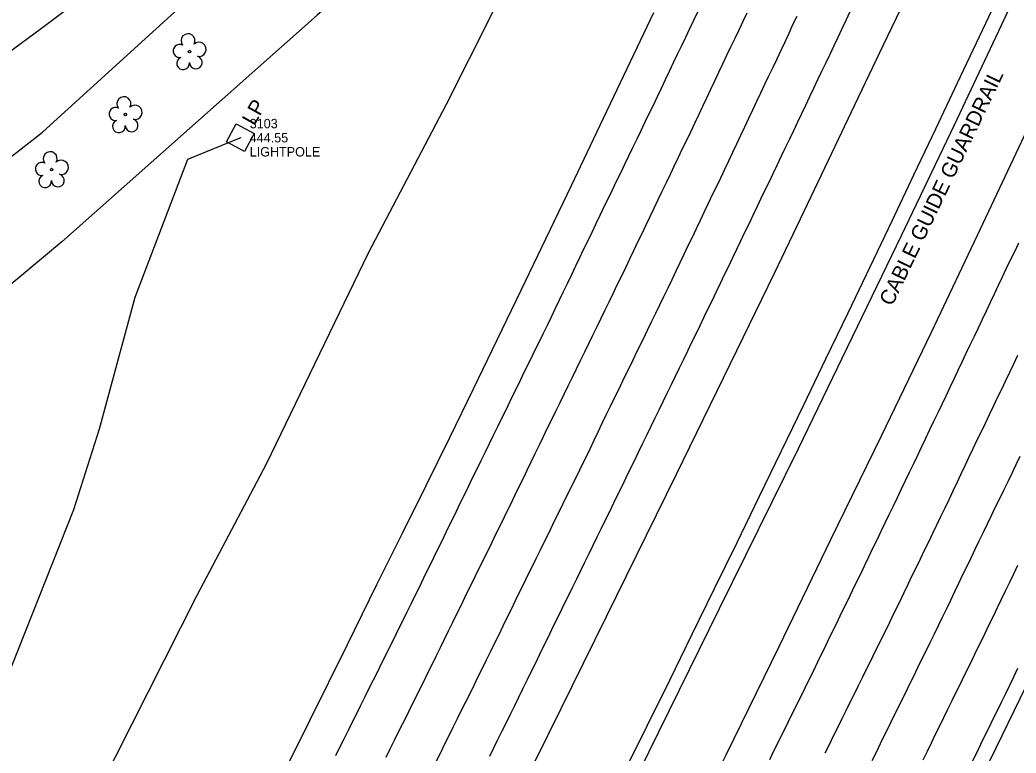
# Model space of a CAD drawing. Extents: x 2074109 to 2077820, y 741079 to 746031.
# Drawn here: x 2075699.8 to 2075964.7, y 743972 to 744166.9 of the extents above; entities that cross this region are included whole.
import ezdxf

# ---------------------------------------------------------------- set-up
doc = ezdxf.new("R2010")
doc.units = 0
for name, color, linetype in [('Exist Guardrail Cable Guide Rail', 7, 'Continuous'), ('Exist Guardrail Cable Guide Rail Text', 7, 'Continuous'), ('Exist Horizontal Alignment', 7, 'Continuous'), ('Exist Roads EOP', 7, 'Continuous'), ('Exist Roads EOT', 7, 'Continuous'), ('Exist Structure Minor Paved Ditch or Gutter', 7, 'Continuous'), ('Exist Utilities Other Pole Cogo Comment', 7, 'Continuous'), ('Exist Utilities Other Pole Cogo Elevation', 7, 'Continuous'), ('Exist Utilities Other Pole Cogo Number', 7, 'Continuous'), ('Exist Utilities Other Pole Text', 7, 'Continuous'), ('Exist Utilities Other Pole With Base CELL', 7, 'Continuous'), ('Exist Utilities Power UG Cable SUE LOS B', 7, 'Continuous'), ('Exist Utilities Telephone UG FO SUE LOS B', 7, 'Continuous'), ('Exist Vegetation Hedge Row', 7, 'Continuous'), ('Exist Vegetation Tree CELL', 7, 'Continuous')]:
    doc.layers.add(name, color=color, linetype=linetype)

msp = doc.modelspace()

# ---------------------------------------------------------------- linework, layer by layer
at = {"layer": 'Exist Guardrail Cable Guide Rail'}
for points in [[(2075948.31, 744139.02), (2075989.39, 744226.34), (2076023.39, 744300.35), (2076049.61, 744359.61), (2076088.84, 744447.64), (2076120.46, 744520.55), (2076157.81, 744608.48)], [(2075650.49, 743554.11), (2075673.2, 743596.24), (2075687.81, 743623.41), (2075710.4, 743665.84), (2075732.48, 743708.32), (2075762.33, 743765.12), (2075783.84, 743808.03), (2075814.02, 743866.81), (2075836.08, 743909.75), (2075849.04, 743935.68), (2075864.46, 743966.93), (2075885.81, 744010.38), (2075906.82, 744052.95), (2075934.19, 744109.59), (2075948.31, 744139.02)]]:
    msp.add_lwpolyline(points, dxfattribs=at)
at = {"layer": 'Exist Horizontal Alignment'}
msp.add_arc((2065746.77, 748969.72), 11283.45, 330.581241, 339.398504, dxfattribs=at)
at = {"layer": 'Exist Roads EOP'}
for points in [[(2075836.75, 743969.63), (2075843.73, 743983.78), (2075855.79, 744008.27), (2075874.4, 744046.14), (2075890.48, 744078.97), (2075900.48, 744099.6), (2075908.34, 744116.01), (2075915.68, 744131.47), (2075922.69, 744146.17), (2075929.46, 744160.26), (2075936.35, 744174.77), (2075943.56, 744190.29), (2075952.83, 744210.32), (2075964.71, 744235.96)], [(2075763.5, 743953.67), (2075776.94, 743980.59), (2075786.97, 744000.87), (2075794.77, 744016.74), (2075801.53, 744030.43), (2075807.8, 744043.11), (2075814.12, 744055.91), (2075820.45, 744068.82), (2075826.74, 744081.8), (2075833.13, 744095.06), (2075839.73, 744108.84), (2075846.46, 744122.91), (2075853.25, 744137.07), (2075860.44, 744152.12), (2075868.38, 744168.9)], [(2075967.54, 744137.56), (2075955.17, 744111.24), (2075942.12, 744083.79), (2075928.82, 744056.24), (2075915.37, 744028.68), (2075901.58, 744000.21), (2075887.58, 743971.62), (2075873.68, 743943.73), (2075859.47, 743915.43), (2075845.49, 743887.94), (2075831.95, 743861.25), (2075818.67, 743835.19), (2075805.35, 743809.58), (2075791.14, 743782.17), (2075777.02, 743754.87), (2075762.95, 743727.43), (2075748.9, 743700.45), (2075734.98, 743673.94), (2075720.91, 743647.46), (2075706.73, 743621.16), (2075693.58, 743599.01), (2075681.89, 743583.08), (2075669.6, 743566.23)], [(2075970.53, 743996.41), (2075954.43, 743963.28), (2075936.6, 743927.16), (2075918.49, 743891.12), (2075900.94, 743856.17), (2075884.58, 743824.12), (2075866.92, 743789.7), (2075848.76, 743754.48), (2075829.89, 743717.88), (2075811.7, 743682.72), (2075794.27, 743649.52), (2075774.29, 743611.67), (2075753.6, 743572.88), (2075735, 743538.43)]]:
    msp.add_lwpolyline(points, dxfattribs=at)
at = {"layer": 'Exist Roads EOT'}
for points in [[(2075783.81, 743971.31), (2075784.93, 743973.54), (2075786.04, 743975.78), (2075787.16, 743978.02), (2075788.27, 743980.26), (2075789.39, 743982.49), (2075790.5, 743984.73), (2075791.62, 743986.97), (2075792.73, 743989.21), (2075793.84, 743991.45), (2075794.95, 743993.69), (2075796.06, 743995.93), (2075797.17, 743998.17), (2075798.28, 744000.41), (2075799.39, 744002.64), (2075800.5, 744004.88), (2075801.61, 744007.12), (2075802.72, 744009.36), (2075803.83, 744011.6), (2075804.94, 744013.84), (2075806.04, 744016.09), (2075807.14, 744018.34), (2075808.24, 744020.58), (2075809.34, 744022.83), (2075810.43, 744025.07), (2075811.53, 744027.32), (2075812.63, 744029.56), (2075813.73, 744031.81), (2075814.82, 744034.06), (2075815.92, 744036.3), (2075817.01, 744038.55), (2075818.1, 744040.8), (2075819.2, 744043.05), (2075820.29, 744045.29), (2075821.39, 744047.54), (2075822.48, 744049.79), (2075823.58, 744052.04), (2075824.67, 744054.28), (2075825.77, 744056.53), (2075826.87, 744058.77), (2075827.97, 744061.02), (2075829.07, 744063.26), (2075830.17, 744065.51), (2075831.27, 744067.75), (2075832.37, 744070), (2075833.46, 744072.25), (2075834.56, 744074.49), (2075835.66, 744076.74), (2075836.76, 744078.98), (2075837.86, 744081.23), (2075838.96, 744083.47), (2075840.06, 744085.72), (2075841.15, 744087.97), (2075842.23, 744090.22), (2075843.31, 744092.48), (2075844.39, 744094.73), (2075845.47, 744096.98), (2075846.55, 744099.24), (2075847.63, 744101.49), (2075848.71, 744103.75), (2075849.79, 744106), (2075850.88, 744108.25), (2075851.96, 744110.51), (2075853.04, 744112.76), (2075854.12, 744115.01), (2075855.21, 744117.26), (2075856.3, 744119.52), (2075857.38, 744121.77), (2075858.47, 744124.02), (2075859.56, 744126.27), (2075860.65, 744128.52), (2075861.73, 744130.77), (2075862.82, 744133.02), (2075863.91, 744135.27), (2075864.99, 744137.52), (2075866.08, 744139.78), (2075867.17, 744142.03), (2075868.24, 744144.28), (2075869.32, 744146.54), (2075870.4, 744148.8), (2075871.47, 744151.05), (2075872.55, 744153.31), (2075873.63, 744155.56), (2075874.7, 744157.82), (2075875.78, 744160.08), (2075876.86, 744162.33), (2075877.93, 744164.59), (2075879.01, 744166.85), (2075880.08, 744169.1)], [(2075893.08, 744168.72), (2075892.01, 744166.46), (2075890.94, 744164.2), (2075889.87, 744161.94), (2075888.8, 744159.68), (2075887.73, 744157.42), (2075886.66, 744155.17), (2075885.59, 744152.91), (2075884.52, 744150.65), (2075883.45, 744148.39), (2075882.38, 744146.13), (2075881.31, 744143.87), (2075880.24, 744141.61), (2075879.17, 744139.35), (2075878.1, 744137.09), (2075877.02, 744134.84), (2075875.93, 744132.59), (2075874.85, 744130.34), (2075873.76, 744128.08), (2075872.68, 744125.83), (2075871.61, 744123.57), (2075870.53, 744121.32), (2075869.45, 744119.06), (2075868.38, 744116.8), (2075867.3, 744114.55), (2075866.23, 744112.29), (2075865.15, 744110.03), (2075864.07, 744107.78), (2075863, 744105.52), (2075861.92, 744103.27), (2075860.85, 744101.01), (2075859.76, 744098.76), (2075858.66, 744096.51), (2075857.56, 744094.27), (2075856.47, 744092.02), (2075855.37, 744089.77), (2075854.28, 744087.52), (2075853.18, 744085.28), (2075852.09, 744083.03), (2075851, 744080.78), (2075849.9, 744078.53), (2075848.81, 744076.28), (2075847.72, 744074.04), (2075846.62, 744071.79), (2075845.53, 744069.54), (2075844.44, 744067.29), (2075843.34, 744065.05), (2075842.25, 744062.8), (2075841.15, 744060.55), (2075840.05, 744058.31), (2075838.96, 744056.06), (2075837.86, 744053.81), (2075836.77, 744051.56), (2075835.68, 744049.31), (2075834.59, 744047.06), (2075833.5, 744044.82), (2075832.4, 744042.57), (2075831.31, 744040.32), (2075830.22, 744038.07), (2075829.13, 744035.82), (2075828.04, 744033.57), (2075826.94, 744031.32), (2075825.85, 744029.08), (2075824.74, 744026.84), (2075823.63, 744024.6), (2075822.52, 744022.36), (2075821.41, 744020.11), (2075820.32, 744017.87), (2075819.22, 744015.62), (2075818.12, 744013.38), (2075817.02, 744011.13), (2075815.92, 744008.89), (2075814.83, 744006.64), (2075813.73, 744004.4), (2075812.63, 744002.15), (2075811.53, 743999.9), (2075810.43, 743997.66), (2075809.33, 743995.41), (2075808.23, 743993.17), (2075807.12, 743990.93), (2075806.01, 743988.69), (2075804.9, 743986.45), (2075803.79, 743984.21), (2075802.67, 743981.98), (2075801.56, 743979.74), (2075800.44, 743977.5), (2075799.33, 743975.26), (2075798.21, 743973.02), (2075797.1, 743970.79)], [(2075810.6, 743969.9), (2075811.71, 743972.15), (2075812.82, 743974.39), (2075813.92, 743976.63), (2075815.03, 743978.87), (2075816.14, 743981.11), (2075817.26, 743983.34), (2075818.38, 743985.58), (2075819.5, 743987.81), (2075820.61, 743990.05), (2075821.71, 743992.3), (2075822.81, 743994.54), (2075823.91, 743996.79), (2075825.01, 743999.03), (2075826.11, 744001.28), (2075827.21, 744003.52), (2075828.3, 744005.77), (2075829.4, 744008.02), (2075830.5, 744010.26), (2075831.6, 744012.51), (2075832.7, 744014.75), (2075833.8, 744017), (2075834.9, 744019.24), (2075836, 744021.48), (2075837.11, 744023.73), (2075838.21, 744025.97), (2075839.31, 744028.21), (2075840.42, 744030.46), (2075841.52, 744032.7), (2075842.62, 744034.94), (2075843.72, 744037.19), (2075844.83, 744039.43), (2075845.93, 744041.67), (2075847.03, 744043.92), (2075848.14, 744046.16), (2075849.24, 744048.4), (2075850.34, 744050.65), (2075851.43, 744052.9), (2075852.5, 744055.16), (2075853.57, 744057.41), (2075854.65, 744059.67), (2075855.74, 744061.92), (2075856.84, 744064.17), (2075857.93, 744066.41), (2075859.03, 744068.66), (2075860.12, 744070.91), (2075861.22, 744073.15), (2075862.31, 744075.4), (2075863.41, 744077.65), (2075864.5, 744079.9), (2075865.6, 744082.14), (2075866.7, 744084.39), (2075867.79, 744086.64), (2075868.88, 744088.89), (2075869.97, 744091.14), (2075871.05, 744093.39), (2075872.14, 744095.64), (2075873.22, 744097.9), (2075874.3, 744100.15), (2075875.38, 744102.41), (2075876.46, 744104.66), (2075877.53, 744106.92), (2075878.61, 744109.17), (2075879.69, 744111.43), (2075880.77, 744113.68), (2075881.85, 744115.94), (2075882.93, 744118.19), (2075884.01, 744120.45), (2075885.09, 744122.7), (2075886.15, 744124.96), (2075887.22, 744127.22), (2075888.29, 744129.48), (2075889.36, 744131.74), (2075890.43, 744134), (2075891.5, 744136.26), (2075892.57, 744138.52), (2075893.64, 744140.78), (2075894.71, 744143.04), (2075895.78, 744145.3), (2075896.85, 744147.55), (2075897.92, 744149.81), (2075898.99, 744152.07), (2075900.06, 744154.33), (2075901.13, 744156.59), (2075902.2, 744158.85), (2075903.26, 744161.12), (2075904.31, 744163.38), (2075905.37, 744165.65), (2075906.44, 744167.91)], [(2075920.47, 744169.05), (2075919.4, 744166.79), (2075918.33, 744164.53), (2075917.26, 744162.27), (2075916.2, 744160.01), (2075915.13, 744157.75), (2075914.06, 744155.49), (2075912.99, 744153.23), (2075911.92, 744150.96), (2075910.86, 744148.7), (2075909.79, 744146.44), (2075908.72, 744144.18), (2075907.64, 744141.93), (2075906.56, 744139.68), (2075905.48, 744137.42), (2075904.4, 744135.17), (2075903.32, 744132.91), (2075902.24, 744130.66), (2075901.16, 744128.4), (2075900.08, 744126.15), (2075899, 744123.89), (2075897.92, 744121.64), (2075896.84, 744119.39), (2075895.76, 744117.13), (2075894.68, 744114.88), (2075893.6, 744112.62), (2075892.52, 744110.37), (2075891.43, 744108.12), (2075890.35, 744105.86), (2075889.27, 744103.61), (2075888.18, 744101.36), (2075887.1, 744099.1), (2075886.02, 744096.85), (2075884.93, 744094.6), (2075883.85, 744092.34), (2075882.77, 744090.09), (2075881.69, 744087.84), (2075880.6, 744085.59), (2075879.5, 744083.34), (2075878.41, 744081.09), (2075877.32, 744078.84), (2075876.23, 744076.59), (2075875.13, 744074.35), (2075874.04, 744072.1), (2075872.95, 744069.85), (2075871.86, 744067.6), (2075870.77, 744065.35), (2075869.67, 744063.1), (2075868.58, 744060.86), (2075867.49, 744058.61), (2075866.4, 744056.36), (2075865.3, 744054.11), (2075864.21, 744051.86), (2075863.12, 744049.61), (2075862.03, 744047.36), (2075860.93, 744045.12), (2075859.84, 744042.87), (2075858.75, 744040.62), (2075857.65, 744038.37), (2075856.55, 744036.13), (2075855.46, 744033.88), (2075854.36, 744031.64), (2075853.26, 744029.39), (2075852.16, 744027.14), (2075851.06, 744024.9), (2075849.96, 744022.65), (2075848.87, 744020.41), (2075847.77, 744018.16), (2075846.67, 744015.92), (2075845.57, 744013.67), (2075844.47, 744011.43), (2075843.37, 744009.18), (2075842.27, 744006.94), (2075841.18, 744004.69), (2075840.08, 744002.44), (2075838.98, 744000.2), (2075837.88, 743997.95), (2075836.78, 743995.71), (2075835.68, 743993.46), (2075834.59, 743991.22), (2075833.49, 743988.97), (2075832.39, 743986.73), (2075831.29, 743984.48), (2075830.18, 743982.24), (2075829.07, 743980), (2075827.96, 743977.76), (2075826.85, 743975.52), (2075825.75, 743973.28), (2075824.64, 743971.04)], [(2075899.18, 743970.27), (2075900.29, 743972.51), (2075901.4, 743974.75), (2075902.51, 743976.99), (2075903.62, 743979.23), (2075904.73, 743981.47), (2075905.84, 743983.71), (2075906.95, 743985.95), (2075908.06, 743988.19), (2075909.15, 743990.44), (2075910.25, 743992.69), (2075911.34, 743994.93), (2075912.44, 743997.18), (2075913.53, 743999.43), (2075914.63, 744001.67), (2075915.72, 744003.92), (2075916.82, 744006.17), (2075917.91, 744008.42), (2075919.01, 744010.66), (2075920.1, 744012.91), (2075921.2, 744015.16), (2075922.29, 744017.4), (2075923.39, 744019.65), (2075924.47, 744021.9), (2075925.56, 744024.16), (2075926.64, 744026.41), (2075927.72, 744028.66), (2075928.8, 744030.92), (2075929.89, 744033.17), (2075930.97, 744035.42), (2075932.05, 744037.68), (2075933.13, 744039.93), (2075934.22, 744042.18), (2075935.3, 744044.44), (2075936.38, 744046.69), (2075937.46, 744048.94), (2075938.55, 744051.2), (2075939.63, 744053.45), (2075940.71, 744055.7), (2075941.78, 744057.96), (2075942.85, 744060.22), (2075943.93, 744062.48), (2075945, 744064.74), (2075946.07, 744066.99), (2075947.15, 744069.25), (2075948.22, 744071.51), (2075949.29, 744073.77), (2075950.37, 744076.02), (2075951.44, 744078.28), (2075952.51, 744080.54), (2075953.59, 744082.8), (2075954.66, 744085.05), (2075955.73, 744087.31), (2075956.81, 744089.57), (2075957.88, 744091.83), (2075958.95, 744094.08), (2075960.02, 744096.34), (2075961.1, 744098.6), (2075962.17, 744100.86), (2075963.24, 744103.12), (2075964.31, 744105.37), (2075965.39, 744107.63)], [(2075965.09, 744077.67), (2075964.01, 744075.41), (2075962.93, 744073.16), (2075961.85, 744070.9), (2075960.77, 744068.65), (2075959.69, 744066.4), (2075958.61, 744064.14), (2075957.53, 744061.89), (2075956.44, 744059.63), (2075955.36, 744057.38), (2075954.28, 744055.13), (2075953.2, 744052.87), (2075952.12, 744050.62), (2075951.06, 744048.36), (2075950, 744046.09), (2075948.95, 744043.82), (2075947.89, 744041.56), (2075946.8, 744039.31), (2075945.71, 744037.06), (2075944.62, 744034.81), (2075943.53, 744032.56), (2075942.45, 744030.31), (2075941.36, 744028.06), (2075940.27, 744025.81), (2075939.18, 744023.55), (2075938.1, 744021.3), (2075937.01, 744019.05), (2075935.92, 744016.8), (2075934.83, 744014.55), (2075933.74, 744012.3), (2075932.65, 744010.05), (2075931.56, 744007.81), (2075930.46, 744005.56), (2075929.35, 744003.32), (2075928.24, 744001.08), (2075927.14, 743998.84), (2075926.03, 743996.6), (2075924.92, 743994.35), (2075923.81, 743992.11), (2075922.7, 743989.87), (2075921.6, 743987.63), (2075920.49, 743985.39), (2075919.38, 743983.15), (2075918.27, 743980.91), (2075917.17, 743978.67), (2075916.06, 743976.42), (2075914.96, 743974.18), (2075913.86, 743971.94)], [(2075965.7, 744050.83), (2075964.62, 744048.57), (2075963.54, 744046.32), (2075962.45, 744044.07), (2075961.35, 744041.82), (2075960.24, 744039.58), (2075959.14, 744037.34), (2075958.06, 744035.08), (2075956.97, 744032.83), (2075955.89, 744030.58), (2075954.81, 744028.33), (2075953.72, 744026.07), (2075952.64, 744023.82), (2075951.56, 744021.57), (2075950.47, 744019.32), (2075949.39, 744017.06), (2075948.31, 744014.81), (2075947.22, 744012.56), (2075946.14, 744010.3), (2075945.05, 744008.05), (2075943.96, 744005.81), (2075942.87, 744003.56), (2075941.77, 744001.31), (2075940.67, 743999.06), (2075939.57, 743996.82), (2075938.47, 743994.58), (2075937.37, 743992.33), (2075936.27, 743990.09), (2075935.16, 743987.84), (2075934.06, 743985.6), (2075932.96, 743983.36), (2075931.86, 743981.11), (2075930.76, 743978.87), (2075929.65, 743976.62), (2075928.55, 743974.38), (2075927.45, 743972.14), (2075926.36, 743969.89)], [(2075939.99, 743970.2), (2075941.09, 743972.45), (2075942.18, 743974.69), (2075943.27, 743976.94), (2075944.38, 743979.19), (2075945.48, 743981.43), (2075946.58, 743983.67), (2075947.68, 743985.92), (2075948.78, 743988.16), (2075949.88, 743990.41), (2075950.98, 743992.65), (2075952.08, 743994.9), (2075953.18, 743997.14), (2075954.28, 743999.39), (2075955.38, 744001.63), (2075956.48, 744003.87), (2075957.57, 744006.13), (2075958.65, 744008.38), (2075959.74, 744010.63), (2075960.83, 744012.88), (2075961.91, 744015.13), (2075963, 744017.39), (2075964.08, 744019.64), (2075965.17, 744021.89)], [(2075965.09, 743994.43), (2075964.01, 743992.18), (2075962.93, 743989.93), (2075961.84, 743987.68), (2075960.74, 743985.43), (2075959.63, 743983.19), (2075958.53, 743980.94), (2075957.43, 743978.7), (2075956.33, 743976.46), (2075955.23, 743974.21), (2075954.13, 743971.97), (2075953.02, 743969.73)]]:
    msp.add_lwpolyline(points, dxfattribs=at)
at = {"layer": 'Exist Structure Minor Paved Ditch or Gutter'}
msp.add_lwpolyline([(2075773.57, 744219.34), (2075752.88, 744201.9), (2075725.45, 744179.61), (2075705.54, 744164.61), (2075687.22, 744151.12), (2075665.75, 744135.87), (2075649.47, 744123.69), (2075626.61, 744108.29), (2075603.41, 744092.8), (2075580.72, 744077.29), (2075560.42, 744063.88), (2075536.19, 744047.58), (2075510.81, 744030.92), (2075480.97, 744010.24), (2075469.41, 744002.69), (2075462.66, 743998.19), (2075458.19, 743995.77), (2075447.97, 743991.11), (2075432.21, 743984.28), (2075417.58, 743978.24), (2075409.83, 743975.03), (2075406.25, 743974.22)], dxfattribs=at)
at = {"layer": 'Exist Utilities Other Pole With Base CELL'}
msp.add_line((2075758.43, 744135.59), (2075758.43, 744135.59), dxfattribs=at)
msp.add_lwpolyline([(2075757.32, 744139.26), (2075762.07, 744136.7), (2075759.51, 744131.94), (2075754.75, 744134.5), (2075757.32, 744139.26)], dxfattribs=at)
msp.add_circle((2075758.43, 744135.59), 0.0707, dxfattribs=at)
at = {"layer": 'Exist Utilities Power UG Cable SUE LOS B'}
msp.add_lwpolyline([(2075533.27, 743615.97), (2075544.83, 743641.27), (2075560.03, 743683.75), (2075587, 743767.88), (2075610.31, 743806.32), (2075628.28, 743837.76), (2075630.55, 743844.53), (2075638.42, 743862.98), (2075655.91, 743905.71), (2075673.35, 743941.84), (2075685.65, 743966.62), (2075697.58, 743994.92), (2075714.14, 744036.7), (2075720.97, 744058.18), (2075730.51, 744093.2), (2075744.47, 744129.88), (2075758.43, 744135.59)], dxfattribs=at)
at = {"layer": 'Exist Utilities Telephone UG FO SUE LOS B'}
msp.add_lwpolyline([(2075647.45, 743807.65), (2075658.54, 743832.13), (2075668.61, 743859.68), (2075684.11, 743893.58), (2075699.83, 743924.49), (2075712.2, 743945.14), (2075746.99, 744013.95), (2075765.38, 744048.88), (2075792.5, 744104.98), (2075813.22, 744144.49), (2075825.37, 744168.63), (2075838.65, 744195.67), (2075851.63, 744219.72), (2075874.79, 744256.54), (2075897.51, 744292.37), (2075909.26, 744310.29), (2075919.16, 744322.32), (2075937.23, 744341.86), (2075954.9, 744371.47)], dxfattribs=at)
at = {"layer": 'Exist Vegetation Hedge Row'}
msp.add_lwpolyline([(2075819.04, 744199.24), (2075807.13, 744185.86), (2075800.28, 744186.97), (2075778.9, 744168.21), (2075710.95, 744107.9), (2075631.89, 744041.9), (2075571.23, 743998.96), (2075557.13, 743983.79), (2075546.74, 743977.4), (2075534.56, 743974.43), (2075526.41, 743978.39), (2075517.94, 743988.2), (2075517.53, 743995.81), (2075526.39, 744007.57), (2075624.05, 744073.17), (2075705.84, 744137.08), (2075778.11, 744202.94), (2075776.25, 744208.85), (2075779.75, 744216.85)], dxfattribs=at)
at = {"layer": 'Exist Vegetation Tree CELL'}
for p, q in [((2075744.92, 744158.5), (2075744.92, 744158.5)), ((2075727.87, 744141.75), (2075727.87, 744141.75)), ((2075708.26, 744127.12), (2075708.26, 744127.12))]:
    msp.add_line(p, q, dxfattribs=at)
for centre in [(2075744.92, 744158.5), (2075727.87, 744141.75), (2075708.26, 744127.12)]:
    msp.add_circle(centre, 0.326, dxfattribs=at)
for centre, radius, start, end in [((2075744.53, 744161.38), 1.86, 330.1651, 219.7134), ((2075742.31, 744158.66), 1.73, 62.6636, 279.3457), ((2075747.47, 744159.09), 1.9, 257.1011, 134.1999), ((2075743.21, 744155.38), 1.69, 111.5671, 6.231), ((2075746.59, 744155.6), 1.7, 181.2822, 74.56), ((2075727.48, 744144.62), 1.86, 330.1651, 219.7134), ((2075725.26, 744141.9), 1.73, 62.6636, 279.3457), ((2075730.41, 744142.34), 1.9, 257.1011, 134.1999), ((2075726.16, 744138.63), 1.69, 111.5671, 6.231), ((2075729.54, 744138.85), 1.7, 181.2822, 74.56), ((2075707.87, 744130), 1.86, 330.1651, 219.7134), ((2075705.65, 744127.28), 1.73, 62.6636, 279.3457), ((2075710.81, 744127.71), 1.9, 257.1011, 134.1999), ((2075706.55, 744124), 1.69, 111.5671, 6.231), ((2075709.93, 744124.22), 1.7, 181.2822, 74.56)]:
    msp.add_arc(centre, radius, start, end, dxfattribs=at)

# ---------------------------------------------------------------- texts
at = {"layer": 'Exist Guardrail Cable Guide Rail Text'}
msp.add_text('CABLE GUIDE GUARDRAIL', height=4, rotation=64.3545, dxfattribs=at).set_placement((2075931.72, 744090.59))
at = {"layer": 'Exist Utilities Other Pole Cogo Comment'}
msp.add_text('LIGHTPOLE', height=2.5, dxfattribs=at).set_placement((2075760.93, 744130.59))
at = {"layer": 'Exist Utilities Other Pole Cogo Elevation'}
msp.add_text('444.55', height=2.5, dxfattribs=at).set_placement((2075760.93, 744134.34))
at = {"layer": 'Exist Utilities Other Pole Cogo Number'}
msp.add_text('3103', height=2.5, dxfattribs=at).set_placement((2075760.93, 744138.09))
at = {"layer": 'Exist Utilities Other Pole Text'}
msp.add_text('LP', height=4, rotation=60.742, dxfattribs=at).set_placement((2075762.14, 744138.57))

doc.saveas('drawing.dxf')
